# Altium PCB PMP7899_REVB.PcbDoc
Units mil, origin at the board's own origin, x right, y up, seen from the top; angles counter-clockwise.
Board outline 4000 x 1400 mil, 4 copper layers (Component Side, Signal Layer 1, Signal Layer 2, Solder Side), stack 61.2 mil thick; 67 components, 29 nets, 152 pads, 45 vias.
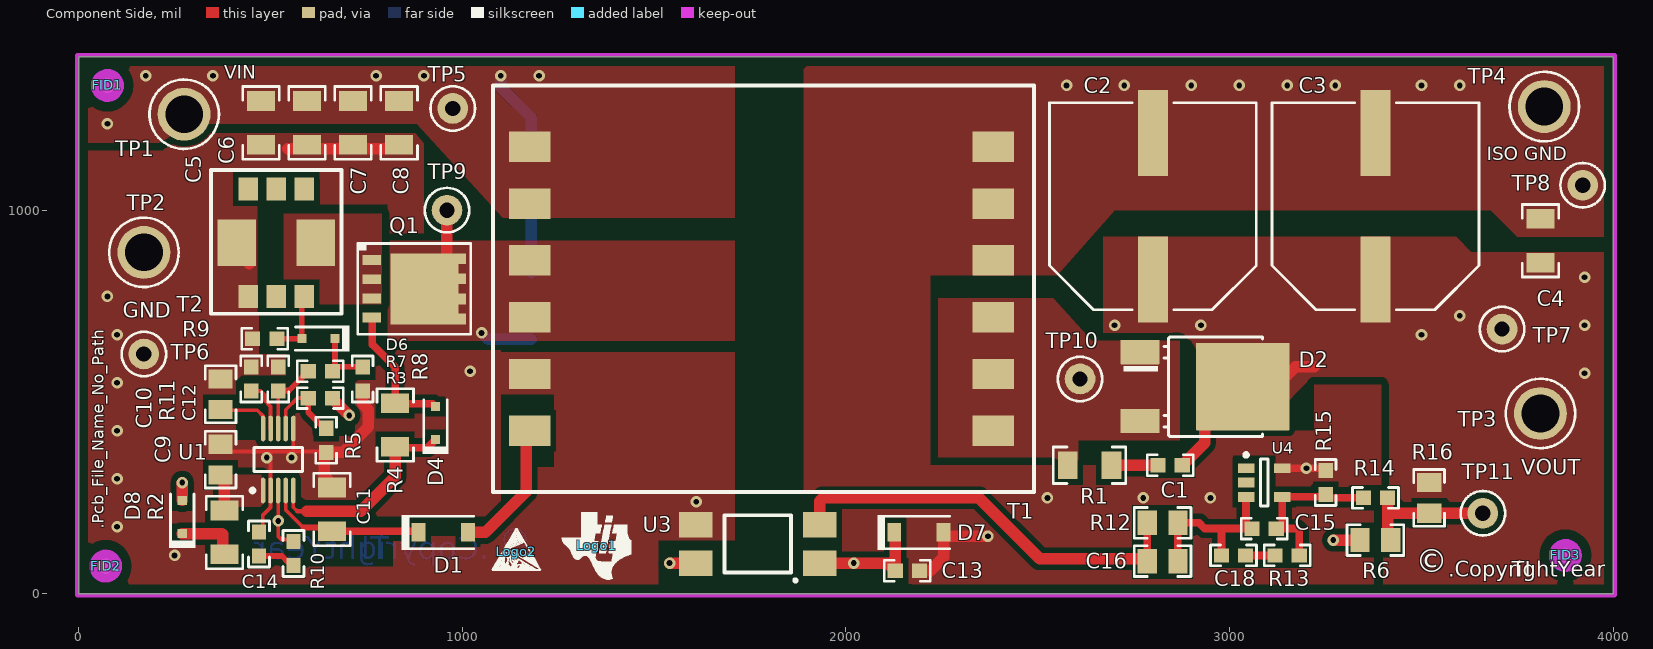
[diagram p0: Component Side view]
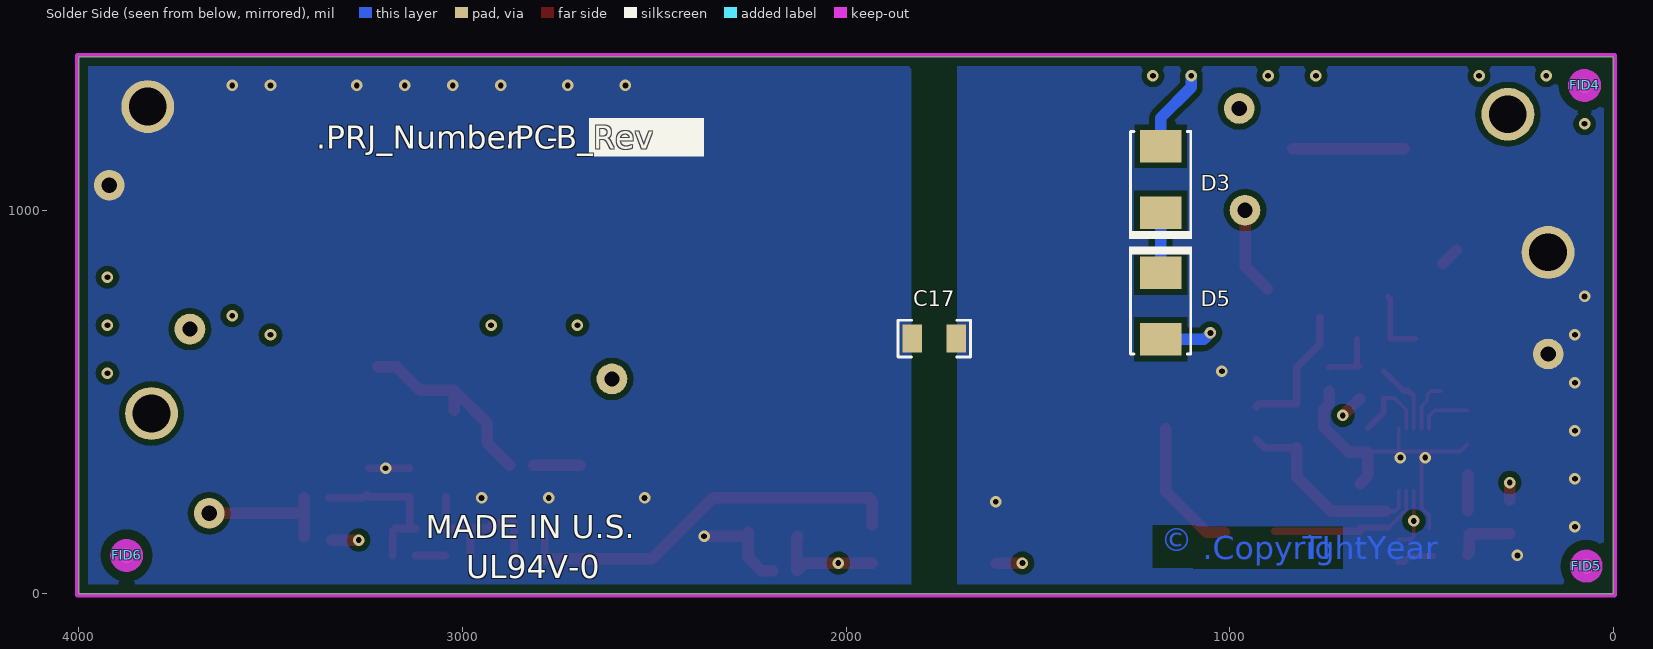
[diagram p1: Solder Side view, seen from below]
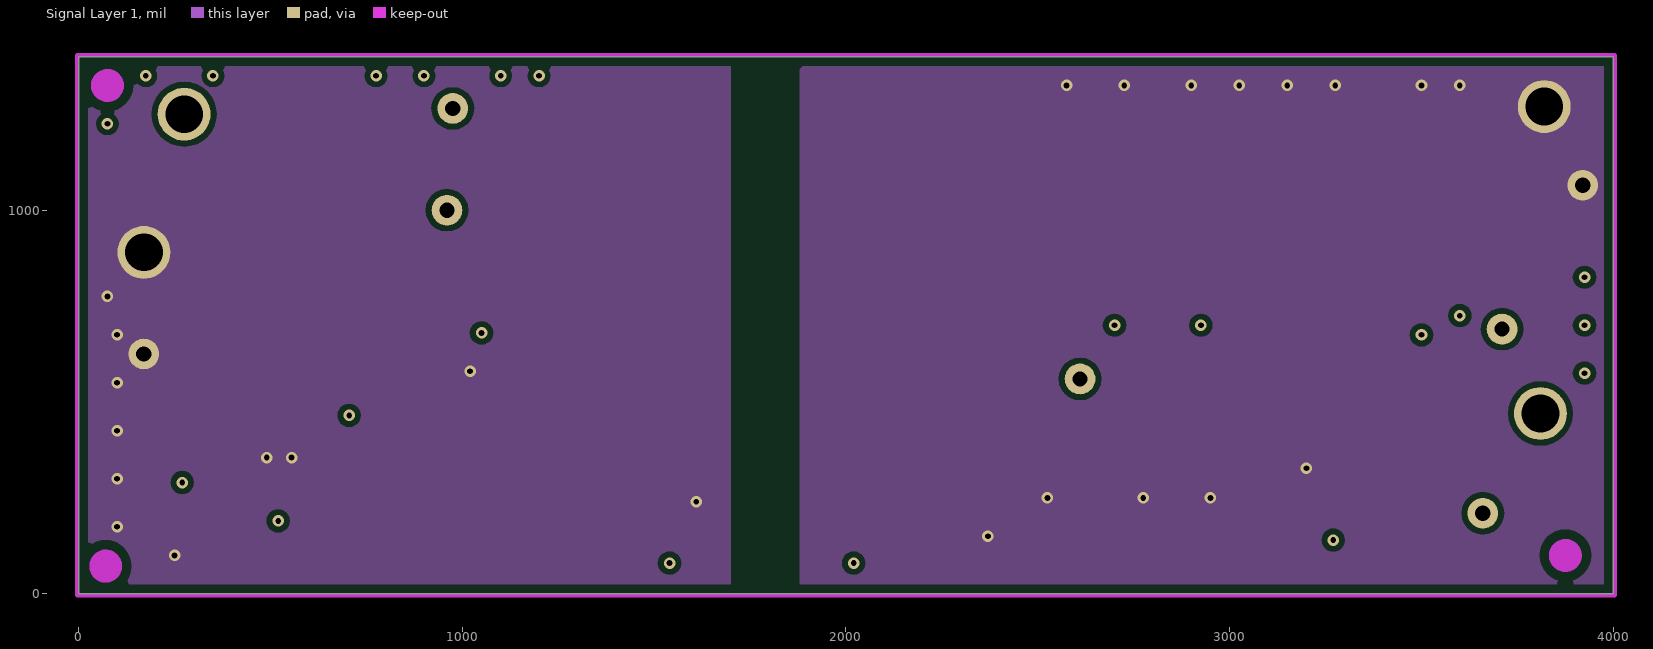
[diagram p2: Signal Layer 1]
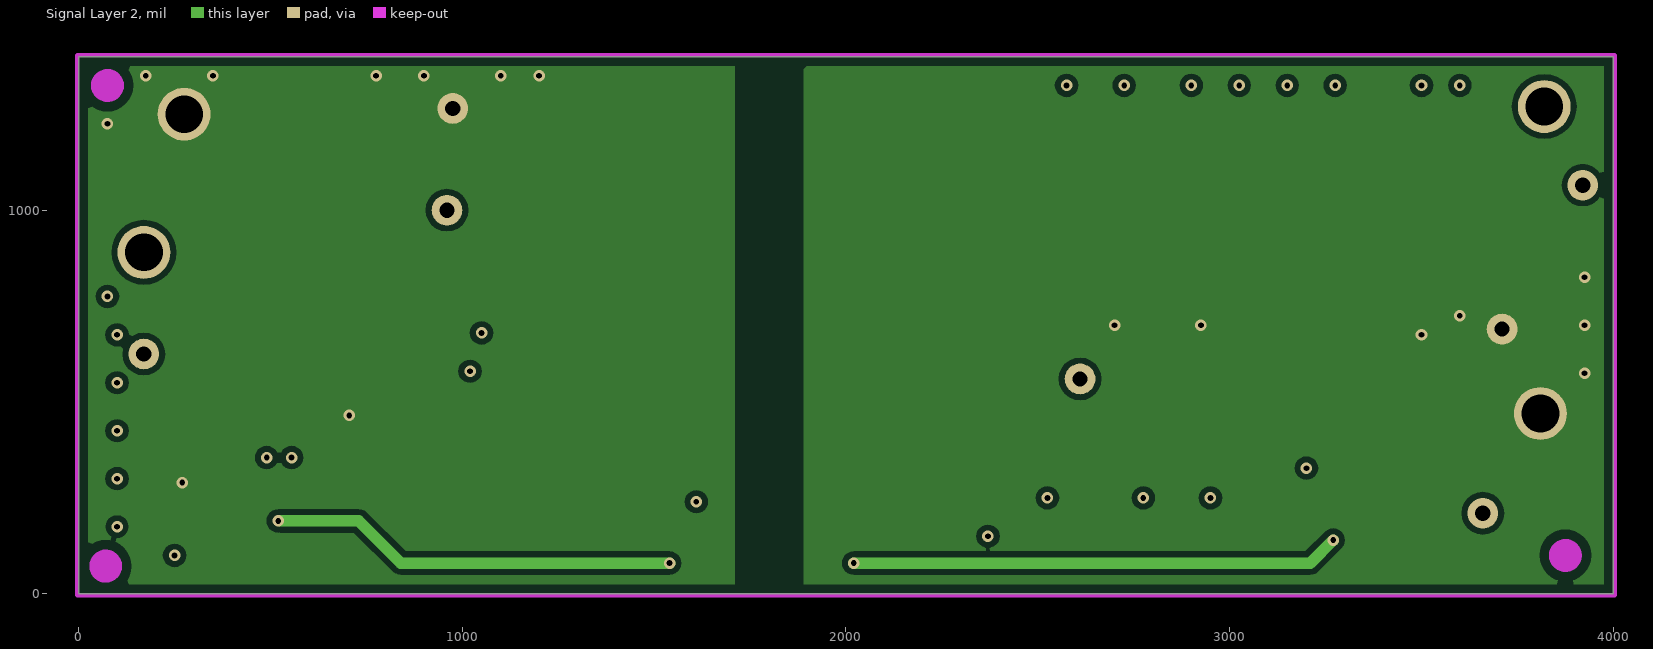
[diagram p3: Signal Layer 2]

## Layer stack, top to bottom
Top Solder: solder mask 0.4, Solder Resist, Dk 3.5
Component Side: signal copper 1.4
Dielectric 1: core 12.5, FR-4, Dk 4.8
Signal Layer 1: signal copper 0.7
Dielectric 2: core 32, FR-4, Dk 4.2
Signal Layer 2: signal copper 0.7
Dielectric 3: core 12.5, FR-4, Dk 4.2
Solder Side: signal copper 1.4
Bottom Solder: solder mask 0.4, Solder Resist, Dk 3.5

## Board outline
0,0 4000,0 4000,1400 0,1400

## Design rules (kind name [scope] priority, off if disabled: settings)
AcuteAngle [All] p1: minimum=4.50000000000000E+0001 checktracksonly=FALSE
AssemblyTestPointUsage [All] p1: valid=2
Clearance Clearance_Poly_to_Poly [IsRegion vs IsRegion] p1: gap=20
Clearance Clearance_Keepouts [((IsTrack Or IsArc) And Not InPoly) And IsFree and IsKeepOut vs ((IsTrack Or IsArc) And Not InPoly) And IsFree and IsKeepOut] p2: gap=0
Clearance Clearance_BoardEdge_MountingHoles [OnCopper and InComponentClass('Mounting Holes') vs IsKeepOut] p3: gap=40
Clearance Clearance_BoardEdge_Poly [OnCopper and InPoly vs IsKeepOut] p4: gap=25
Clearance Clearance_BoardEdge [OnCopper and Not InComponentClass('Logo') and not InComponentClass('FiducialMark') and not InRegion(1000,500,4000,800) and Not IsKeepout vs IsKeepOut] p5: gap=35
Clearance Clearance_Poly [InPolygon] p6: gap=15
Clearance [All] p7: gap=7.87
ComponentClearance ComponentClearance_MountingHoles_FiducialMarks [InComponentClass('Mounting Holes') vs InComponentClass('FiducialMark')] p1: gap=50 collisioncheckmode=3 verticalgap=10 showdistances=FALSE
ComponentClearance ComponentClearance_Shunt [InComponentClass('Header') vs InComponentClass('Shunt')] p2: gap=0 collisioncheckmode=3 verticalgap=0 showdistances=FALSE
ComponentClearance ComponentClearance_Logo [InComponentClass('Logo')] p3: gap=50 collisioncheckmode=3 verticalgap=10 showdistances=FALSE
ComponentClearance ComponentClearance_ScrewToNut [(HasFootprint('NY PMS 440 0025 PH')) vs (HasFootprint('Keystone_1902C'))] p4: gap=5 collisioncheckmode=3 verticalgap=10 showdistances=FALSE
ComponentClearance ComponentClearance_MountingHoles [InComponentClass('Mounting Holes')] p5: gap=250 collisioncheckmode=3 verticalgap=100000 showdistances=FALSE
ComponentClearance ComponentClearance_SmallPassives [HasFootprint('0201*') or HasFootprint('0402*') or HasFootprint('0508') or HasFootprint('0603*') or HasFootprint('0612') or HasFootprint('0805*') or HasFootprint('0815*') or HasFootprint('0830*') or HasFootprint('1206*') or HasFootprint('1210*') or HasFootprint('1808*') or HasFootprint('1812*') or HasFootprint('1825*') or HasFootprint('2010*') or HasFootprint('2220*') or HasFootprint('2225*') or HasFootprint('2512*') or HasFootprint('2728*') or HasFootprint('3518*') vs HasFootprint('0201*') or HasFootprint('0402*') or HasFootprint('0508') or HasFootprint('0603*') or HasFootprint('0612') or HasFootprint('0805*') or HasFootprint('0815*') or HasFootprint('0830*') or HasFootprint('1206*') or HasFootprint('1210*') or HasFootprint('1808*') or HasFootprint('1812*') or HasFootprint('1825*') or HasFootprint('2010*') or HasFootprint('2220*') or HasFootprint('2225*') or HasFootprint('2512*') or HasFootprint('2728*') or HasFootprint('3518*')] p6: gap=20 collisioncheckmode=3 verticalgap=10 showdistances=FALSE
ComponentClearance ComponentClearance_THtoSMT [IsThruComponent vs IsSMTComponent] p7: gap=50 collisioncheckmode=3 verticalgap=30 showdistances=FALSE
ComponentClearance ComponentClearance_THtoTH [IsThruComponent vs IsThruComponent] p8: gap=50 collisioncheckmode=3 verticalgap=30 showdistances=FALSE
ComponentClearance [All] p9: gap=20 collisioncheckmode=3 verticalgap=10 showdistances=FALSE
DiffPairsRouting [All] p1: maxlimit=100 minlimit=10 mostfreqgap=10 toplayer_minwidth=15 toplayer_maxwidth=15 toplayer_prefwidth=15 midlayer1_minwidth=15 midlayer1_maxwidth=15 midlayer1_prefwidth=15 midlayer2_minwidth=15 midlayer2_maxwidth=15 midlayer2_prefwidth=15 bottomlayer_minwidth=15 bottomlayer_maxwidth=15 bottomlayer_prefwidth=15 maxuncoupledlength=1000
FabricationTestPointUsage TestPointUsage [All] p1: valid=2 allowmultiple=FALSE
FabricationTestpoint Testpoint [All] p1: side=3 testpointundercomponent=TRUE minsize=40 maxsize=100 preferedsize=60 minholesize=0 maxholesize=40 preferedholesize=32 testpointgrid=1 allowsidetop=TRUE allowsidebottom=TRUE usegrid=TRUE gridtolerance=0.01
FanoutControl Fanout_LCC [IsLCC] p1: bgadir=Out bgaviamode=Centered fanoutstyle=Auto fanoutdirection=Alternating viagrid=1 // Fanout_LCC (Default Rule)
FanoutControl Fanout_BGA [IsBGA] p2: bgadir=Out bgaviamode=Centered fanoutstyle=Auto fanoutdirection=Alternating viagrid=1 // Fanout_BGA (Default Rule)
FanoutControl Fanout_Default [All] p4: bgadir=Out bgaviamode=Centered fanoutstyle=Auto fanoutdirection=Alternating viagrid=1 // Fanout_Default (Default Rule)
FanoutControl Fanout_Small [(CompPinCount < 5)] p5: bgadir=Out bgaviamode=Centered fanoutstyle=Auto fanoutdirection=OutThenIn viagrid=1 // Fanout_Small (Default Rule)
HoleSize [All] p1: absolutevalues=TRUE maxlimit=251 minlimit=8 maxpercent=80.000 minpercent=20.000
MinimumAnnularRing MinimumAnnularRing_ThermalPadVias [IsVia and InAnyComponent] p1: minimumring=5.91
MinimumAnnularRing [All] p2: minimumring=6
MinimumSolderMaskSliver MinimumSolderMaskSliver_Logo [InComponentClass('Logo') vs InComponentClass('Logo')] p1: minsoldermaskwidth=0.7
MinimumSolderMaskSliver [All] p2: minsoldermaskwidth=3.94
PlaneConnect [All] p1: planeconnectstyle=Relief reliefexpansion=10 reliefentries=4 reliefconductorwidth=10 reliefairgap=10
PolygonConnect [All] p1: connectstyle=Direct reliefconductorwidth=10 reliefentries=4 polygonreliefangle="90 Angle" airgapwidth=10
RoutingVias ThermalPadVias [IsVia and InAnyComponent] p1: holewidth=7.87 width=19.68 viastyle="Through Hole" minholewidth=7.87 minwidth=19.68 maxholewidth=12.99 maxwidth=23.62
RoutingVias [All] p2: holewidth=16 width=34 viastyle="Through Hole" minholewidth=7.87 minwidth=26 maxholewidth=40 maxwidth=65
SilkToBoardRegionClearance [Not ((IsComment or IsDesignator) And (Hide <> 'False')) and not InRegion(1000,500,4000,800)] p1:
SilkToSilkClearance SilkToSilkClearance_Pb-FreeLogo [(HasFootprint('Pb-Free_Overlay_Medium') OR HasFootprint('Pb-Free_Overlay_Small')) vs (HasFootprint('Pb-Free_Overlay_Medium') OR HasFootprint('Pb-Free_Overlay_Small'))] p1: silktosilkclearance=0
SilkToSilkClearance [All] p2: silktosilkclearance=5
SilkToSolderMaskClearance "Silk to Solder Mask Opening" [All] p1: minsilkscreentomaskgap=1 clearancetoexposedcopper=FALSE
SolderMaskExpansion [All] p1: expansion=1.97
UnpouredPolygon [All] p1: allowunpoured=FALSE
Width [All] p1: maxlimit=100 minlimit=6 preferedwidth=10 checkconnectedcopper=TRUE
14 further rules are at their usual default settings.

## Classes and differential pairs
component class FiducialMark: FID1 FID2 FID3 FID4 FID5 FID6
component class Logo: Logo1

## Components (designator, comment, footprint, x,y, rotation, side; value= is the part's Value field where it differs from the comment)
C1 "DNP" 0603 2845,335 r180 top
C2 "EEV-FK1J151Q" SM_RADIAL_H13 2800,1010 r90 top
C3 "EEV-FK1J151Q" SM_RADIAL_H13 3380,1010 r90 top
C4 "C3216X7R2A105M" 1206 3810,920 r90 top
C5 "GRM31CR71E106KA12L" 1206 475,1227.52 r270 top
C6 "GRM31CR71E106KA12L" 1206 595,1227.52 r270 top
C7 "GRM31CR71E106KA12L" 1206 715,1227.52 r270 top
C8 "GRM31CR71E106KA12L" 1206 835.32,1227.52 r270 top
C9 "C2012X5R1E105K" 0805_HV 370,350 r90 top
C10 "C2012C0G1E103J" 0805_HV 370,520 r90 top
C11 "GRM31CR61E106KA12L" 1206 660,220 r90 top
C12 "C1608C0G1H101J" 0603 520,560 r90 top
C13 "GRM188R61C105KA93D" 0603 2160,60 r0 top
C14 "DNP" 0603 470,130 r90 top
C15 "C1608C0G2A101J" 0603 3090,170 r0 top
C16 "DNP" 0805_HV 2825,85 r180 top
C17 "C1206C102KFRACTU" 1206 1770,665 r180 bottom
C18 "C0603C104J3RACTU" 0603 3010,100 r180 top
D1 "1N4148W-7-F" SOD-123 950,160 r0 top
D2 "MURHD560T4G" DPAK 2900,540 r0 top
D3 "1SMB5939BT3G" SMB 1180,1080 r90 bottom
D4 "DNP" sod-323 930,445 r90 top
D5 "MBRS1100T3G" SMB 1180,750 r270 bottom
D6 "BAT54HT1G" sod-323 625,665 r180 top
D7 "MMSZ4699-V" SOD-123 2190,160 r0 top
D8 "BAT54HT1G" sod-323 270,200 r90 top
FID1 "Fiducial" Fiducial10-20 75,1325 r0 top
FID2 "Fiducial" Fiducial10-20 70.46,72.11 r0 top
FID3 "Fiducial" Fiducial10-20 3875,100 r0 top
FID4 "Fiducial" Fiducial10-20 75,1325 r180 bottom
FID5 "Fiducial" Fiducial10-20 70.46,72.11 r180 bottom
FID6 "Fiducial" Fiducial10-20 3875,100 r180 bottom
Logo1 "Texas Instruments" TI_Symbol_Overlay_Small 1350,125 r0 top
Logo2 "ESD Susceptible" ESD_Overlay_Small 1140,110 r0 top
Q1 "BSC067N06LS3 G" PG-TDSON-8 875,795 r0 top
R1 "DNP" 1206 2635,335 r180 top
R2 "CRCW12063R30JNEA" 1206 380,160 r270 top
R3 "CRCW060346K4FKEA" 0603 630,510 r0 top
R4 "CRCW12060000Z0EA" 1206 825,440 r270 top
R5 "CRCW060310K0FKEA" 0603 645,400 r90 top
R6 "CRCW080510K0FKEA" 0805_HV 3380,140 r0 top
R7 "CRCW06031K00FKEA" 0603 630,580 r0 top
R8 "CRCW06032R74FKEA" 0603 740,560 r90 top
R9 "CRCW060310K0FKEA" 0603 485,665 r0 top
R10 "DNP" 0603 560,105 r270 top
R11 "CRCW060349K9FKEA" 0603 450,560 r270 top
R12 "CRCW0805499RFKEA" 0805_HV 2825,185 r0 top
R13 "CRCW06038K25FKEA" 0603 3150,100 r180 top
R14 "CRCW060340K2FKEA" 0603 3380,250 r0 top
R15 "CRCW06031K05FKEA" 0603 3250,290 r90 top
R16 "ERJ-6GEYJ470V" 0805_HV 3520,250 r90 top
T1 "NA6264-AL" NA62XX-AL 1780,795 r0 top
T2 "PA1005.100NLT" PA1005.XXXNL 515,915 r0 top
TP1 "VIN" Keystone1502-2 275,1250 r0 top
TP2 "GND" Keystone1502-2 170,890 r0 top
TP3 "VOUT" Keystone1502-2 3810,470 r0 top
TP4 "ISO GND" Keystone1502-2 3820,1270 r0 top
TP5 "5000" Keystone5000 975,1265 r0 top
TP6 "5001" Keystone5001 170,625 r0 top
TP7 "5000" Keystone5000 3710,690 r0 top
TP8 "5001" Keystone5001 3920,1065 r0 top
TP9 "5002" Keystone5002 960,1000 r0 top
TP10 "5002" Keystone5002 2610,560 r0 top
TP11 "5002" Keystone5002 3660,210 r0 top
U1 "LM5022MME/NOPB" MUB10A_N 520,350 r90 top
U3 "PS2501L-1-L-A" PS2501L 1770,130 r180 top
U4 "LMV431ACM5/NOPB" MF05A_N 3090,290 r0 top

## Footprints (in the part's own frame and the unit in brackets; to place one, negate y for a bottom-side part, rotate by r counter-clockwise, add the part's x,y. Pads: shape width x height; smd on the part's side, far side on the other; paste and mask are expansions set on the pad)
0603 [mm] "0603 from SM-752 data"
  rect 1x0.95 smd: 1(-0.8,0) 2(0.8,0)
  silkscreen extent -1.52,-0.69 1.52,0.69, body extent -0.87,-0.47 0.87,0.47, height 0.85
0805_HV [mil] "0805 with 30mil clearance between pads"
  rect 50x63 smd: 1(-40,0) 2(40,0)
  silkscreen extent -74,-40 74,40, body extent -43,-29 43,29, height 43
1206 [mm] "1206 from SM-752 data"
  rect 1.3x1.85 smd: 1(-1.45,0) 2(1.45,0)
  silkscreen extent -2.4,-1.21 2.4,1.21, body extent -1.7,-0.9 1.7,0.9, height 1.35
DPAK [mm] "D-PAK, 3-Pads, Body 6.22x6.73mm (max), TO-252AA using nominal STEP model"
  rrect6% 2.6x1.6 smd: 1(-3.4,2.28) 3(-3.4,-2.28)
  rrect2% 6.2x5.8 smd paste-2.9: 4(3.4,0)
  silkscreen extent -4.5,-3.3 4.7,3.28, body extent -3.86,-3.29 5.84,3.29, height 2.48
ESD_Overlay_Small [mil]
  silkscreen extent -62,-48 64,61
Fiducial10-20 [mm]
  round 1 smd paste-0.5 mask+0.5: 1(0,0)
  Keep-Out Layer circle w1.178: c0,0 r0.5
Keystone1502-2 [mm] "Double Turret"
  round 3.5 hole 2.5: 1(0,0)
  silkscreen extent -2.3,-2.3 2.3,2.3, body extent -1.61,-1.61 1.61,1.61, height 5.56
Keystone5000 [mil] "For Keystone 500x miniature loop terminals"
  round 80 hole 40: 1(0,0)
  silkscreen extent -58,-58 58,58, body extent -49,-49 49,49, height 182
Keystone5001 [mil] "For Keystone 500x miniature loop terminals"
  round 80 hole 40: 1(0,0)
  silkscreen extent -58,-58 58,58, body extent -49,-49 49,49, height 182
Keystone5002 [mil] "For Keystone 500x miniature loop terminals"
  round 80 hole 40: 1(0,0)
  silkscreen extent -58,-58 58,58, body extent -49,-49 49,49, height 182
MF05A_N [mm] "SOT23, 5-Leads, Body 2.9x1.6mm, Pitch 0.95mm, Lead Span 2.8mm, IPC Medium Density"
  rect 1.1x0.65 smd: 1(-1.2,0.95) 2(-1.2,0) 3(-1.2,-0.95) 4(1.2,-0.95) 5(1.2,0.95)
  silkscreen extent -1.32,-1.55 0.25,1.95, body extent -0.9,-1.55 0.9,1.55, height 1.19
MUB10A_N [mm] "TSSOP, 10-Leads, Body 3x3mm, Pitch 0.5mm, IPC Medium Density"
  oval 1.7x0.3 smd: 1(-2.05,1) 2(-2.05,0.5) 3(-2.05,0) 4(-2.05,-0.5) 5(-2.05,-1) 6(2.05,-1) 7(2.05,-0.5) 8(2.05,0) 9(2.05,0.5) 10(2.05,1)
  silkscreen extent -2.17,-1.6 0.8,1.82, body extent -1.6,-1.6 1.6,1.6, height 1.09
NA62XX-AL [mil] "COILCRAFT TRANFORMER"
  round 60 on Top Overlay: 0(-750,370)
  rect 108x79 smd: 1(-604,370) 2(-604,222) 3(-604,74) 4(-604,-74) 5(-604,-222) 6(-604,-370) 7(604,-370) 8(604,-222) 9(604,-74) 10(604,74) 11(604,222) 12(604,370)
  silkscreen extent -700,-530 710,530, body extent -700,-530 710,530, height 560
PA1005.XXXNL [mil] "PULSE ENGINEERING PA1005.XXXNL SERIES"
  round 30 on Top Overlay: 0(-145,-225)
  rect 50x60 smd: 1(-73,-140) 2(0,-140) 3(73,-140) 4(73,140) 5(0,140) 6(-73,140)
  rect 100x120 smd: 7(103,0) 8(-103,0)
  silkscreen extent -170,-185 170,190, body extent -170,-185 170,190, height 190
PG-TDSON-8 [mm] "Infineon recommended land pattern"
  rect 1.2x0.65 smd: 1(-2.825,1.905) 2(-2.825,0.635) 3(-2.825,-0.635) 4(-2.825,-1.905)
  rect 0.5x0.7 smd: 5(3.175,-2) 6(3.175,-0.675) 7(3.175,0.675) 8(3.175,2)
  rect 4.5x4.7 smd paste-2.25: 9(0.675,0)
  silkscreen extent -3.74,-3 3.74,3, body extent -3.17,-2.89 3.17,2.9, height 1.1
PS2501L [mm] "NEC optocoupler"
  rect 2.2x1.7 smd: 1(-4.1,1.27) 2(-4.1,-1.27) 3(4.1,-1.27) 4(4.1,1.27)
  silkscreen extent -2.57,-1.9 2.2,2.49, body extent -3.5,-2.47 3.5,2.47, height 3.8
SM_RADIAL_H13 [mm] "12.5 x 13.5mm:  Panasonic H13"
  rect 5.7x2 smd: 1(-4.85,0) 2(4.85,0)
  silkscreen extent -6.85,-6.85 6.85,6.85, body extent -6.85,-6.85 6.85,6.85, height 14
SMB [mil] "Molded Diode, 2-Leads, Body 5.4x3.6mm, IPC Medium Density, based on OnSemi component dimensions"
  rect 85x107.99 smd: 1(-87.01,0) 2(87.01,0)
  silkscreen extent -155,-82 125,82, body extent -106,-71 106,71, height 91
SOD-123 [mm] "On Semi recommended land pattern"
  rect 0.915x1.22 smd: 1(-1.637,0) 2(1.637,0)
  silkscreen extent -2.74,-1.17 2.03,1.17, body extent -1.93,-0.9 1.93,0.9, height 1.35
sod-323 [mm] "NXP recommended land pattern"
  rect 0.6x0.6 smd paste-0.05: 1(-1.1,0) 2(1.1,0)
  silkscreen extent -2.06,-0.86 1.53,0.86, body extent -1.3,-0.67 1.3,0.68, height 1.1
TI_Symbol_Overlay_Small [mil]
  silkscreen extent -90,-88 91,88

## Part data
C1: library part C1608C0G2A101J, "CAP, CERM, 100pF, 100V, +/-5%, C0G/NP0, 0603"
C2 C3: "CAP, AL, 150uF, 63V, +/-20%, 0.16 ohm, SMD"
C4: "CAP, CERM, 1uF, 100V, +/-20%, C Series, 1206"
C5 C6 C7 C8: "CAP, CERM, 10uF, 25V, +/-10%, X7R, 1206"
C9: "CAP, CERM, 1uF, 25V, +/-10%, X5R, 0805"
C10: "CAP, CERM, 0.01uF, 25V, +/-5%, C0G/NP0, 0805"
C11: "CAP, CERM, 10uF, 25V, +/-10%, X5R, 1206"
C12: "CAP, CERM, 100pF, 50V, +/-5%, C0G/NP0, 0603"
C13: "CAP, CERM, 1uF, 16V, +/-10%, X5R, 0603"
C14: library part C0603C104K3RACTU, "CAP, CERM, 0.1uF, 25V, +/-10%, X7R, 0603"
C15: "CAP, CERM, 100pF, 100V, +/-5%, C0G/NP0, 0603"
C16: library part C2012X7R1H102K, "CAP, CERM, 1000 pF, 50 V, +/- 10%, X7R, 0805"
C17: "CAP CER 1000PF 1.5KV X7R 1206"
C18: "CAP, CERM, 0.1uF, 25V, +/-5%, X7R, 0603"
D1: "Diode, Ultrafast, 100V, 0.15A, SOD-123"
D2: "Ultra-Fast Diode 600V, 5A, DPAK"
D3: "Diode, Zener, 39 V, 550 mW, SMB"
D4: library part BAT54HT1G, "Diode, Schottky, 30V, 0.2A, SOD-323"
D5: "Diode, Schottky, 100 V, 1 A, SMB"
D6 D8: "Diode, Schottky, 30V, 0.2A, SOD-323"
D7: "Diode, Zener, 12V, 500mW, SOD-123"
FID1 FID2 FID3 FID4 FID5 FID6: "Fiducial mark.  There is nothing to buy or mount."
Logo1: library part TI_Logo, "Texas Instrument Corporate Signature"
Logo2: library part ESD_Susceptible, "ESD Susceptible Symbol"
Q1: "MOSFET, N-CH, 60V, 50A, PG-TDSON-8"
R1: library part CRCW1206100RFKEA, "RES, 100, 1%, 0.25 W, 1206"
R2: "RES, 3.3, 5%, 0.25 W, 1206"
R3: "RES, 46.4k ohm, 1%, 0.1W, 0603"
R4: "RES, 0 ohm, 5%, 0.25W, 1206"
R5 R9: "RES, 10.0k ohm, 1%, 0.1W, 0603"
R6: "RES, 10.0k ohm, 1%, 0.125W, 0805"
R7: "RES, 1.00k ohm, 1%, 0.1W, 0603"
R8: "RES, 2.74, 1%, 0.1 W, 0603"
R10: library part CRCW06031K00FKEA, "RES, 1.00k ohm, 1%, 0.1W, 0603"
R11: "RES, 49.9k ohm, 1%, 0.1W, 0603"
R12: "RES, 499 ohm, 1%, 0.125W, 0805"
R13: "RES, 8.25 k, 1%, 0.1 W, 0603"
R14: "RES, 40.2k ohm, 1%, 0.1W, 0603"
R15: "RES, 1.05 k, 1%, 0.1 W, 0603"
R16: "RES, 47, 5%, 0.125 W, 0805"
T1: "COILCRAFT TRANSFORMER"
T2: "XFRMR CURR SENSE 2.0MH 1:100 SMD"
TP1 TP2 TP3 TP4: library part 1502-2, "Terminal, Turret, TH, Double"
TP5 TP7: "Test Point, TH, Miniature, Red"
TP6 TP8: "Test Point, TH, Miniature, Black"
TP9 TP10 TP11: "Test Point, TH, Miniature, White"
U1: "60V Low Side Controller for Boost and SEPIC, 10-pin MSOP, Pb-Free"
U3: "High Isolation Voltage Single Transistor Type OptoCoupler 200-400% CTR"
U4: "Low-Voltage (1.24V) Adjustable Precision Shunt Regulators, 5-pin SOT-23, Pb-Free"

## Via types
v1: diameter 30, hole 15, Component Side to Solder Side, 45 vias

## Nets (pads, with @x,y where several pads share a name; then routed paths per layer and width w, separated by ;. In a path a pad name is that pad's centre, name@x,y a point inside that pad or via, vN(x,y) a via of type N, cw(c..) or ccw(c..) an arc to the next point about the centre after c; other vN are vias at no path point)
COMP: R10.1 U1.3 U3.4 | length 1292
  Component Side w10: U1.3 v1(520,190) 520,150 528.5,141.5 R10.1@560,141.5
  Component Side w30: v1(1540,80) U3.4
  Signal Layer 2 w30: v1@525,190 730,190 840,80 v1(1540,80)
CS: C12.1 R7.1 U1.8 | length 188.3
  Component Side w10: U1.8 C12.1@520,521.46
  Component Side w15: C12.1@527.05,521.46 535.59,530 547.2,530 547.2,528.7 R7.1
GND: C5.2 C6.2 C7.2 C8.2 C9.2 C10.2 C11.2 C12.2 C14.2 C17.2 R5.1 R8.1 R9.1 R11.1 T1.5 T2.1 T2.8 TP2.1 TP6.1 U1.2 U1.6 U3.3 | length 1208.1
  Component Side w10: C9.2@380,390 399.37,370.63 500,370.63 ; C14.2@480,171.5 480,205 500.31,225.31 U1.2 500.31,370.31 500,370.63 ; U1.6 559.37,370.63 ; R5.1@640,368.5 637.87,370.63 559.37,370.63 ; 500,370.63 559.37,370.63
  Component Side w30: T2.8@410,895 T2.8@445,860 ; 545.32,1160.43 C8.2@835.32,1160.43 ; C11.2@660,287.09 640,307.09 640,368.5 R5.1 688.5,368.5 755,435 755,480 740,495 R8.1
  other v1: 250,100 100,175 1610,240 100,300 490,355 555,355 100,425 100,550 1020,580 100,675 75,775
"ISO GND": C2.2 C3.2 C4.2 C13.2 C17.1 D7.2 R15.2 T1.10 T1.11 T1.12 TP4.1 TP8.1 U4.5 | length 354
  Component Side w20: U4.5 R15.2@3244.09,327.4
  Component Side w30: C13.2 2220,60 2255,95 2254.47,95.53 D7.2 ; D7.2@2266.05,150 2340,150 v1(2370,150)
  other v1: 2525,250 2775,250 2950,250 3200,327.4 2575,1325 2725,1325 2900,1325 3025,1325 3150,1325 3275,1325 3500,1325 3600,1325
NetC1_2: C1.2 R1.1 | length 121.4
  Component Side w30: R1.1 C1.2
NetC13_1: C13.1 D7.1 R6.1 U3.1 | length 1641.5
  Component Side w30: U3.1 v1(2020,80) 2108.5,80 C13.1 2128.5,147.03 D7.1@2125.53,150 ; v1(3270,140) R6.1
  Signal Layer 2 w30: v1(2020,80) 3210,80 v1(3270,140)
NetC14_1: C14.1 R10.2 | length 98.1
  Component Side w15: C14.1 530.04,98.5 546.04,82.5 R10.2@560,82.5 ; C14.1@478.54,98.5 C14.1@480,98.5
NetC15_1: C15.1 C16.1 C18.2 R12.2 U4.3 | length 458.8
  Component Side w20: C16.1 R12.2 2920,185 2935,170 2978.5,170 ; C18.2 2978.5,170 ; U4.3 3042.76,185.75 C15.1 2978.5,170
NetC15_2: C15.2 R13.1 R14.1 R15.1 U4.4 | length 426
  Component Side w20: C15.2 3175,170 3181.5,163.5 R13.1 ; C15.2@3137.24,170 U4.4 3244.09,252.6 R15.1 3258.5,250 R14.1
NetC16_2: C16.2 R12.1 U3.2 | length 1084.8
  Component Side w20: C16.2 R12.1
  Component Side w30: U3.2 1931.42,241.42 1940,250 2346,250 2505,91 2784,91 C16.2@2785,90
NetC18_1: C18.1 R13.2 | length 77
  Component Side w20: C18.1@3044.94,100 R13.2@3121.95,100
NetD1_2: D1.2 T1.6 | length 359.4
  Component Side w30: D1.2 1060,160 1166,266 T1.6@1166,430
NetD2_1: D2.1 D2.3 R1.2 T1.7 T1.8 T1.9 TP10.1
NetD3_1: D3.1 D5.1 | length 156
  Solder Side w30: D5.1 D3.1
NetD4_2: D4.2 Q1.4 R4.1 | length 358.1
  Component Side w20: Q1.4 765,718.78 765,650 825,590 825,495 923.31,495 D4.2
NetD5_2: D5.2 Q1.5 Q1.6 Q1.7 Q1.8 Q1.9 T1.3 T1.4 TP9.1 | length 366.4
  Component Side w30: Q1.9 960,853.43 TP9.1@959.82,1000.12
  Solder Side w30: v1(1050,680) 1067.01,662.99 D5.2
NetD6_1: D6.1 R7.2 R8.2 | length 154.8
  Component Side w15: D6.1 668.31,596.81 662.99,591.5 R8.2 R8.2@741.5,590
NetD6_2: D6.2 R9.2 T2.3 | length 177.8
  Component Side w15: R9.2 D6.2 581.69,768.69 T2.3
NetD8_1: D8.1 R2.2 | length 159.9
  Component Side w30: D8.1 373.31,156.69 375,155 375,107.91 R2.2
NetQ1_1: Q1.1 Q1.2 Q1.3 T2.7
NetR6_2: R6.2 R14.2 R16.1 TP11.1 | length 349.8
  Component Side w30: R6.2@3411.5,148.5 3411.5,210 ; R14.2 3411.5,210 ; TP11.1@3659.82,210.12 3411.5,210
OUT: D4.1 R4.2 U1.5 | length 540.5
  Component Side w10: U1.5 559.37,225.63 570,215
  Component Side w12: 570,215 595,215
  Component Side w20: R4.2@825,380.94 909.25,380.94 D4.1
  Component Side w30: 595,215 735,215 825,305 R4.2@825,380.94
RT: R11.2 U1.9 | length 133.1
  Component Side w10: R11.2 474.76,528.5 485,518.27 485,503.5 500.31,488.19 U1.9
SS: C10.1 U1.10 | length 139.6
  Component Side w10: C10.1@380,478.5 465.51,478.5 480.63,463.39 U1.10
UVLO: R3.1 R5.2 U1.7 | length 216
  Component Side w10: U1.7 539.68,479.68 570,510 R3.1
  Component Side w15: R3.1 598.5,472.99 R5.2@640,431.5
VCC: C11.1 D1.1 U1.4 | length 412.6
  Component Side w10: U1.4 539.68,218.58 585.35,172.91
  Component Side w15: 585.35,172.91 C11.1@660,172.91
  Component Side w20: C11.1 D1.1@882.62,162.91
VIN: C5.1 C6.1 C7.1 C8.1 D3.2 D8.2 R3.2 T1.1 T1.2 TP1.1 TP5.1 | length 317.3
  Component Side w30: D8.2 v1(270,290) ; R3.2@661.5,508.5 v1@700,470
  Solder Side w30: v1(1100,1350) 1100,1320 1180,1240 D3.2
  other v1: 705,465 75,1225 175,1350 350,1350 775,1350 900,1350 1200,1350
"VIN U1": C9.1 R2.1 U1.1 | length 92.9
  Component Side w30: R2.1 C9.1@380,310
VOUT: C1.1 C2.1 C3.1 C4.1 D2.4 R16.2 TP3.1 TP7.1 | length 530.6
  Component Side w30: C1.1 2935,393.5 2935,444.51 D2.4@3020.49,530 ; D2.4@3020.49,479 D2.4@3020.49,530 ; 3220,591.5 3171.5,591.5 3110,530 D2.4@3020.49,530
  other v1: 3925,575 3500,675 2700,700 2925,700 3925,700 3600,725 3925,825
pads on no net: FID1.1 FID2.1 FID3.1 FID4.1 FID5.1 FID6.1 T1.0 T2.0 T2.2 T2.4 T2.5 T2.6 U4.1 U4.2

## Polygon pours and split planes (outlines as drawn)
"ISO GND" on Component Side "Top Layer-ISO GND" (solid, pour order 25): 1890,0 1890,265 3376.32,265 3375,263.68 3375,0
"ISO GND" on Component Side "Top Layer-ISO GND" (solid, remove dead copper, pour order 27): 4000,1400 1890,1400 1890,265 2355,265 2490,125 3010,128.54 3011.26,360.87 3120,360 3120,280 3395,278.54 3395,545 3220,545 3220,425 2955,425 2876.5,335 2220,335 2220,830 2550.65,830 2700,1000 3680,1000 3750,930 4000,930
NetD2_1 on Component Side "Top Layer-D2_1" (solid, remove dead copper, pour order 29): 2240,770 2540,770 2640,660 2849.92,659.92 2850,660 2870,659.92 2870,400.08 2605,399.99 2605,340 2240,340
GND on Component Side "Top Layer-GND" (solid, pour order 28): 390,400 560,400 560,470 604.55,470 610,410 720,410 721.3,550 720,550 720,635 1100,635 1100,202.5 575,202.5 575,320 390,319.41
"VIN U1" on Component Side "Top Layer-VIN U1" (solid, remove dead copper, pour order 20): 370,310 370,226.93 473.07,226.93 485,225.98 485,310
VIN on Component Side "Top Layer-VIN" (solid, pour order 19): 0,1175 210,1175 300,1225 881.57,1225 1105,980 1710,980 1710,1400 0,1400
GND on Component Side "Top Layer-GND" (solid, remove dead copper, pour order 24): 0,705 410,705 410,74.14 820,70 820,150 1050,150 1050,330 1240,330 1240,520 1050,520 1050,630 1710,630 1710,140 1510,140 1510,0 0,0
GND on Component Side "Top Layer-GND" (solid, pour order 23): 290,730 470,730 470,625 540,625 540,570 425,570 410,555 410,535 290,535
NetQ1_1 on Component Side "Top Layer-Q1_1" (solid, remove dead copper, pour order 21): 790,755 790,990 535,990 535,785 615,785 615,755
NetD5_2 on Component Side "Top Layer-D5_2" (solid, remove dead copper, pour order 22): 1710,920 1710,660 805,660 805,920
VOUT on Component Side "Top Layer-VOUT" (solid, remove dead copper, pour order 30): 2670,930 3590,930 3630,890 4000,890 4000,0 3400,0 3400,560 3238.85,560 3238.7,550 3200,550 3130,480 3130,430 2920,430 2920,625.71 2900,660 2850,680 2670,680
GND on Component Side "Top Layer-GND" (solid, remove dead copper, pour order 26): 0,675 465,675 465,1080 630,1080 630,1015 805,1015 805,920 900,920 900,1195 895,1200 220,1200 220,1155 0,1155
VIN on Signal Layer 2 "MidLayer2-VIN" (solid, remove dead copper, pour order 31): 0,0 0,1400 1710,1400 1710,0
VOUT on Signal Layer 2 "MidLayer2-VOUT" (solid, remove dead copper, pour order 32): 4005,1400 1890,1400 1890,-5 4000,-5
"ISO GND" on Solder Side "Bottom Layer-ISO GND" (solid, remove dead copper, pour order 34): 4005,1400 1830,1400 1830,0 4005,0
GND on Solder Side "Bottom Layer-GND" (solid, remove dead copper, pour order 33): 1710,1400 0,1400 0,0 1710,0
GND on Signal Layer 1 "MidLayer1-GND" (solid, remove dead copper, pour order 35): -5,1400 1700,1400 1700,0 0,0
"ISO GND" on Signal Layer 1 "MidLayer1-ISO GND" (solid, remove dead copper, pour order 36): 4000,1400 1880,1400 1880,0 4000,0

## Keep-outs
Keep-Out Layer:
  lines w10: 3999.97,1405 0,1405 ccw(c0,1400) -5,1400 -5,0 ccw(c0,0) 0,-5 4000,-5 ccw(c4000,0) 4005,0 4005,1399.98 ccw(c3999.98,1399.98) 3999.98,1405
  text ".Layer_Name" at 577,-858.49 h60

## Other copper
Component Side:
  text ".Layer_Name" at 577,-858.49 h60
Solder Side:
  text "TI" at 810,90 h60
  text ".CopyrightYear" at 1070,90 h60
  text "©" at 1180,90 h105
  text ".Layer_Name" at 577,-858.49 h60

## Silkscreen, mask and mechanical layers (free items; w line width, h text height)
Top Overlay:
  text ".Pcb_File_Name_No_Path" at 65,170 h30 r90
  text ".CopyrightYear" at 3570,45 h40
  text "TI" at 3735,45 h40
  text "©" at 3485,35 h105
  text ".Layer_Name" at 577,-858.49 h60
Bottom Overlay:
  rectangle: 2370,1140 2670,1240
  text "-" at 2780,1160 h60
  text ".PCB_Rev" at 2890,1160 h60
  text ".PRJ_Number" at 3381,1160.5 h60
  text "MADE IN U.S." at 3095,145 h60
  text "UL94V-0" at 2990,40 h60
  text ".Layer_Name" at 577,-858.49 h60
Top Paste:
  text ".Layer_Name" at 577,-858.49 h60
Bottom Paste:
  text ".Layer_Name" at 577,-858.49 h60
Top Solder:
  text ".Layer_Name" at 577,-858.49 h60
  text ".Layer_Name" at 577,-858.49 h60
Bottom Solder:
  text ".Layer_Name" at 577,-858.49 h60
Drill Guide:
  text ".Layer_Name" at 577,-858.49 h60
Mechanical 1:
  the board outline again, w10
  text ".Layer_Name" at 577,-858.49 h60
Mechanical 2:
  rectangle: 125,-400 500,-275
  rectangle: 0,-275 125,-150
  lines w7: 0,-275 1000,-275 ; 125,-400 125,-150 ; 250,-400 250,-150 ; 500,-400 500,-150 ; 750,-400 750,-150 ; 0,-400 0,-150 1000,-150 1000,-400 0,-400
  text ".Layer_Name" at 577,-858.49 h60
Mechanical 3:
  text ".Layer_Name" at 577,-858.49 h60
Mechanical 4:
  text ".Layer_Name" at 577,-858.49 h60
Mechanical 5:
  lines w10: -292,-930.17 6308,-930.17 ; -292,-726.83 6310,-726.83 ; -292,-523.5 -292,-1133.5 3713,-1133.5 6310,-1133.5 6310,-523.5 -291.5,-523.5 -291.5,-1133.5 1284,-1133.5 ; 2173,-1133.5 2173,-523.5 ; 3440,-726.83 3440,-523.5 ; 4280,-726.83 4280,-523.5 ; 4902,-1140 4902,-937.17
  text "COMPONENTS MARKED 'DNP' SHOULD NOT BE POPULATED." at 1153.5,-318.5 h60
  text "ASSEMBLY VARIANT:" at 1153,-434 h60
  text ".VariantName" at 2189,-434 h60
  text "PCB VIEWED FROM TOP SIDE" at -228.5,-655.67 h60
  text "BOARD #:" at 2248,-655.67 h60
  text ".PRJ_Number" at 2793.5,-655.67 h60
  text "REV:" at 3638,-655.67 h60
  text ".PCB_Rev" at 3929.5,-655.67 h60
  text "SVN REV:" at 4476,-655.67 h60
  text ".VersionControl_RevNumber" at 4982,-655.67 h60
  text "PLOT NAME =" at -228.5,-1064.34 h60
  text ".plot_File_Name" at 577,-1064.34 h60
  text "GENERATED    :" at 2250,-1064.34 h60
  text ".Print_Date" at 3119.5,-1064.34 h60
  text ".Print_Time" at 3848.5,-1064.34 h60
  text "TEXAS INSTRUMENTS" at 5113,-1064.34 h60
Mechanical 6:
  lines w10: -292.5,-727.33 6309.5,-727.33 ; -290.5,-930.67 6309.5,-930.67 ; 1115.5,-1140.5 1115.5,-937.67 ; 1737.5,-727.33 1737.5,-524 ; 2577.5,-727.33 2577.5,-524 ; 3844.5,-1134 3844.5,-524 ; 4733.5,-1134 6309,-1134 6309,-524 -292.5,-524 -292.5,-1134 2304.5,-1134 6309.5,-1134 6309.5,-524
  text "COMPONENTS MARKED 'DNP' SHOULD NOT BE POPULATED." at 6102,-318 h60
  text ".VariantName" at 5058,-434 h60
  text "ASSEMBLY VARIANT:" at 6097,-434 h60
  text ".VersionControl_RevNumber" at 1035.5,-656.17 h60
  text "SVN REV:" at 1541.5,-656.17 h60
  text ".PCB_Rev" at 2088,-656.17 h60
  text "REV:" at 2379.5,-656.17 h60
  text ".PRJ_Number" at 3224,-656.17 h60
  text "BOARD #:" at 3769.5,-656.17 h60
  text "PCB VIEWED FROM BOTTOM SIDE" at 6246,-656.17 h60
  text "TEXAS INSTRUMENTS" at 904.5,-1064.84 h60
  text ".Print_Time" at 2169,-1064.84 h60
  text ".Print_Date" at 2898,-1064.84 h60
  text "GENERATED    :" at 3767.5,-1064.84 h60
  text ".plot_File_Name" at 5440.5,-1064.84 h60
  text "PLOT NAME =" at 6246,-1064.84 h60
Mechanical 9:
  drawing of 57 lines, arcs and shapes, not listed
  text "1" at 739.84,8036.5 h70
  text "2" at 3235.5,8036.5 h70
  text "3" at 5724.84,8036.5 h70
  text "4" at 8231.51,8036.5 h70
  text "5" at 10730.5,8036.5 h70
  text "6" at 13235.5,8036.5 h70
  text "A" at -416.5,6893.5 h70
  text "A" at 14383.5,6893.5 h70
  text "B" at -416.5,4513.5 h70
  text "B" at 14383.5,4513.5 h70
  text "C" at -416.5,2138.5 h70
  text "C" at 14383.5,2138.5 h70
  text "PROJECT TITLE:" at 11343.5,277.5 h45
  text ".PRJ_Title" at 11393.5,144.17 h70
  text "DESIGNED FOR:" at 11343.5,-23.5 h45
  text ".PRJ_Customer" at 11393.5,-163.5 h70
  text "D" at -416.5,-231.5 h70
  text "D" at 14383.5,-231.5 h70
  text "FILE NAME:" at 11343.5,-323.5 h45
  text ".PCB_File_Name_No_Path" at 11393.5,-443.5 h70
  text "Texas Instruments (TI) and/or its licensors do not warrant the accuracy or completeness of this specification" at 6374,-605.34 h45
  text "ENGINEER:" at 11343.5,-613.5 h45
  text "LAYOUT BY:" at 12848.5,-613.5 h45
  text "or any information contained therein. TI and/or its licensors do not warrant that this design will meet" at 6329.01,-718 h45
  text ".PRJ_Engineer" at 11393.5,-768.49 h70
  text ".PCB_Layout" at 12899,-768.49 h70
  text "the specifications, will be suitable for your application or fit for any particular purpose, or will operate in" at 6329.01,-830.67 h45
  text ".Layer_Name" at 577,-858.49 h60
  text "ALTIUM DESIGNER VERSION:" at 12848.5,-923.5 h45
  text "an implementation. TI and/or its licensors do not warrant that the design is production worthy. You should" at 6329.01,-943.33 h45
  text "completely validate and test your design implementation to confirm the system functionality for your application." at 6374,-1056 h45
  text ".print_Scale" at 11393.5,-1056.83 h70
  text ".Application_BuildNumber" at 12899,-1056.83 h70
  text "1" at 739.84,-1263.5 h70
  text "2" at 3235.5,-1263.5 h70
  text "3" at 5724.84,-1263.5 h70
  text "4" at 8231.51,-1263.5 h70
  text "5" at 10730.5,-1263.5 h70
  text "6" at 13235.5,-1263.5 h70
Mechanical 10:
  drawing of 185 lines, arcs and shapes, not listed
  text "DESIGN INFORMATION" at 12381.02,5910 h60
  text "MIN. TRACK WIDTH:" at 11736.46,5730 h60
  text "8" at 12832.7,5730 h60
  text "MIL" at 12987.46,5730 h60
  text "MIN. CLEARANCE:" at 11736.46,5598 h60
  text "0.2" at 12772.7,5598 h60
  text "mm" at 12987.46,5598 h60
  text "MIN. VIA PAD SIZE:" at 11736.46,5466 h60
  text "15" at 12802.71,5466 h60
  text "MIL" at 12987.46,5466 h60
  text "0.05mm (2MIL)" at 12431.46,5324.29 h60
  text "MINIMUM ANNULAR RING" at 11407.23,5320 h60
  text "EXTERNAL" at 13139.46,5320 h60
  text "PER" at 11607.23,5202 h60
  text "IPC-D-275 CLASS 2 LEVEL C" at 11827.23,5202 h60
  text "MIL, HOLES" at 13315.46,5089.71 h60
  text "+/-" at 12923,5089 h60
  text "+/-" at 13777,5089 h60
  text "REGISTRATION TOLERANCES:" at 11407.23,5084 h60
  text "METAL" at 12607,5084 h60
  text "5" at 13183.2,5084 h60
  text "3" at 14016.2,5084 h60
  text "MIL" at 14132.46,5084 h60
  text "MATERIAL:" at 11332.46,4874.54 h60
  text "FR-4 High Tg" at 12318.9,4734.21 h60
  text "FR-408" at 11753.46,4725.64 h60
  text "X" at 12165.46,4725.64 h60
  text "OTHER" at 13241.46,4725.64 h60
  text "62 MIL (1.6mm) +/-10%" at 12073.56,4562.92 h60
  text "THICKNESS:" at 11407.23,4558.64 h60
  text "X" at 11945.4,4558.64 h60
  text "OTHER" at 13358.46,4558.64 h60
  text "TOLERANCE:" at 11407.23,4400.64 h60
  text "X" at 12246.53,4400.64 h60
  text "ANSI IPC-6012 TYPE 3 CLASS 2" at 12433.48,4400.64 h60
  text "OTHER +/-" at 12433.46,4244.64 h60
  text "BOW & TWIST:" at 11407.23,4087.64 h60
  text "X" at 12246.53,4087.64 h60
  text "ANSI IPC-6012 TYPE 3 CLASS 2" at 12433.48,4087.64 h60
  text "OTHER +/-" at 12433.46,3929.13 h60
  text "DRILLING:" at 11332.46,3790.64 h60
  text "REFERENCE:" at 11407.23,3673.64 h60
  text "X" at 12055.46,3673.64 h60
  text "AS SHOWN" at 12242.46,3673.64 h60
  text "X" at 12956.46,3673.64 h60
  text "NC_DRILL FILES" at 13093.46,3673.64 h60
  text "PTH MIN COPPER THICKNESS:" at 11407.23,3515.64 h60
  text "X" at 12757.46,3515.64 h60
  text "1MIL" at 12894.46,3515.64 h60
  text "OTHER" at 13391.46,3515.64 h60
  text "BOARD FINISH:" at 11332.46,3356.64 h60
  text "SILKSCREEN:" at 11487.68,3238.64 h60
  text "X" at 12436.46,3238.64 h60
  text "TOP" at 12562.46,3238.64 h60
  text "X" at 12946.46,3238.64 h60
  text "BOTTOM" at 13073.46,3238.64 h60
  text "SILKSCREEN COLOR:" at 11487.68,3071.64 h60
  text "X" at 12435.42,3071.64 h60
  text "WHITE" at 12562.46,3071.64 h60
  text "OTHER" at 13073.46,3071.64 h60
  text "SOLDER RESIST COLOR:" at 11487.68,2901.64 h60
  text "X" at 12055.42,2742.44 h60
  text "GREEN" at 12182.46,2742.44 h60
  text "BLUE" at 12773.46,2742.44 h60
  text "OTHER" at 13311.46,2742.44 h60
  text "IMMERSION GOLD (ENIG)" at 12393.46,2553.92 h60
  text "ENEPIG" at 13731,2550.64 h60
  text "SURFACE FINISH:" at 11332.46,2549.64 h60
  text "X" at 11500,2395 h60
  text "IMM. TIN/SILVER OR EQUIV" at 11662,2392.64 h60
  text "OTHER" at 13093.46,2392.64 h60
  text "ARRAY/PANEL:" at 11332.46,2213.64 h60
  text "X" at 12210,2210 h60
  text "CUT AND TRIM PER MECH LAYER 1" at 12393.46,2209.35 h60
  text "N.C. ROUTE" at 12393.46,2057.64 h60
  text "V. SCORE" at 13259.46,2057.64 h60
  text "CERTIFICATION:" at 11332.46,1920.64 h60
  text "MATERIALS AND WORKMANSHIP FOR ALL PCBS" at 12057.46,1920.64 h60
  text "TO MEET OR EXCEED THE REQUIREMENTS OF:" at 12057.46,1822.64 h60
  text "X" at 11683.96,1686.13 h60
  text "ANSI IPC-A-600F CLASS ->" at 11822.96,1686.13 h60
  text "X" at 13462.02,1686.13 h60
  text "2" at 13580.96,1686.14 h60
  text "1" at 13265.96,1684.64 h60
  text "3" at 13934.96,1684.64 h60
  text "X" at 11686.02,1526.64 h60
  text "UL 94V-0" at 11822.96,1526.64 h60
  text "X" at 12498.02,1526.64 h60
  text "RoHS" at 12634.96,1526.64 h60
  text "OTHER" at 13279.36,1526.64 h60
  text "PER ORDER" at 13676.42,1526.64 h60
  text "ADDITIONAL REQUIREMENTS:" at 11332.46,1385.64 h60
  text "MICROSECTION:" at 11407.23,1270.64 h60
  text "YES" at 12312.96,1270.64 h60
  text "REQUIRED" at 13174.46,1114.49 h60
  text "BARE BOARD ELEC. TEST:" at 11407.23,1111.64 h60
  text "NONE" at 12712.96,1111.64 h60
  text "PER ORDER" at 13766.46,1111.64 h60
  text "X" at 12590,1110 h60
  text "MANUFACTURER'S UL:" at 11407.23,954.64 h60
  text "RAIL" at 12572.96,950.35 h60
  text "METAL" at 13064.77,950.35 h60
  text "X" at 13440,950 h60
  text "SILK" at 13576.46,950.35 h60
  text ".Layer_Name" at 577,-858.49 h60
Mechanical 11:
  lines w10: -292,-930.17 6308,-930.17 ; -292,-726.83 6310,-726.83 ; -292,-523.5 -292,-1133.5 3713,-1133.5 6310,-1133.5 6310,-523.5 -291.5,-523.5 -291.5,-1133.5 1284,-1133.5 ; 2173,-1133.5 2173,-523.5 ; 3440,-726.83 3440,-523.5 ; 4280,-726.83 4280,-523.5 ; 4902,-1140 4902,-937.17
  text "ALL ARTWORK VIEWED FROM TOP SIDE" at -228.5,-655.67 h60
  text "BOARD #:" at 2248,-655.67 h60
  text ".PRJ_Number" at 2793.5,-655.67 h60
  text "REV:" at 3638,-655.67 h60
  text ".PCB_Rev" at 3929.5,-655.67 h60
  text "SVN REV:" at 4476,-655.67 h60
  text ".VersionControl_RevNumber" at 4982,-655.67 h60
  text "LAYER NAME =" at -228.5,-858.49 h60
  text "PLOT NAME =" at -228.5,-1064.34 h60
  text ".plot_File_Name" at 577,-1064.34 h60
  text "GENERATED    :" at 2250,-1064.34 h60
  text ".Print_Date" at 3119.5,-1064.34 h60
  text ".Print_Time" at 3848.5,-1064.34 h60
  text "TEXAS INSTRUMENTS" at 5113,-1064.34 h60
Mechanical 12:
  drawing of 295 lines, arcs and shapes, not listed
  text "Layer" at 9790.58,7830 h60
  text "Name" at 10200.49,7830 h60
  text "Material" at 11140.23,7830 h60
  text "Thickness" at 12000,7830 h60
  text "Constant" at 12649.83,7830 h60
  text "Board Layer Stack" at 13219.69,7830 h60
  text "1" at 9790.58,7710 h60
  text "Top Overlay" at 10200.49,7710 h60
  text "2" at 9790.58,7590 h60
  text "Top Solder" at 10200.49,7590 h60
  text "Solder Resist" at 11140.23,7590 h60
  text "0.40mil" at 12000,7590 h60
  text "3.5" at 12649.83,7590 h60
  text "3" at 9790.58,7470 h60
  text "Component Side" at 10200.49,7470 h60
  text "Copper" at 11140.23,7470 h60
  text "1.40mil" at 12000,7470 h60
  text "4" at 9790.58,7350 h60
  text "Dielectric 1" at 10200.49,7350 h60
  text "FR-4" at 11140.23,7350 h60
  text "12.50mil" at 12000,7350 h60
  text "4.8" at 12649.83,7350 h60
  text "5" at 9790.58,7230 h60
  text "Signal Layer 1" at 10200.49,7230 h60
  text "Copper" at 11140.23,7230 h60
  text "0.70mil" at 12000,7230 h60
  text "6" at 9790.58,7110 h60
  text "Dielectric 2" at 10200.49,7110 h60
  text "FR-4" at 11140.23,7110 h60
  text "32.00mil" at 12000,7110 h60
  text "4.2" at 12649.83,7110 h60
  text "7" at 9790.58,6990 h60
  text "Signal Layer 2" at 10200.49,6990 h60
  text "Copper" at 11140.23,6990 h60
  text "0.70mil" at 12000,6990 h60
  text "8" at 9790.58,6870 h60
  text "Dielectric 3" at 10200.49,6870 h60
  text "FR-4" at 11140.23,6870 h60
  text "12.50mil" at 12000,6870 h60
  text "4.2" at 12649.83,6870 h60
  text "9" at 9790.58,6750 h60
  text "Solder Side" at 10200.49,6750 h60
  text "Copper" at 11140.23,6750 h60
  text "1.40mil" at 12000,6750 h60
  text "10" at 9790.58,6630 h60
  text "Bottom Solder" at 10200.49,6630 h60
  text "Solder Resist" at 11140.23,6630 h60
  text "0.40mil" at 12000,6630 h60
  text "3.5" at 12649.83,6630 h60
  text "11" at 9790.58,6510 h60
  text "Bottom Overlay" at 10200.49,6510 h60
  text ".Layer_Name" at 577,-858.49 h60
Mechanical 13:
  text ".Layer_Name" at 577,-858.49 h60
Mechanical 14:
  text ".Layer_Name" at 577,-858.49 h60
Mechanical 15:
  text ".Layer_Name" at 577,-858.49 h60
Mechanical 16:
  text ".Layer_Name" at 577,-858.49 h60
Drill Drawing:
  circle w1: c5572.72,3221.04 r24.89
  lines w1: 5547.83,2909.96 5560.27,2909.96 5572.72,2897.52 5585.16,2909.96 5597.6,2909.96 5585.16,2922.4 5597.6,2934.85 5585.16,2934.85 5572.72,2947.29 5560.27,2934.85 5547.83,2934.85 5560.27,2922.4 5547.83,2909.96 ; 5547.83,3096.61 5597.6,3096.61 5572.72,3046.84 5547.83,3096.61
  lines w12: 5480,2852.72 7598.02,2852.72 ; 5480,3300.68 7598.02,3300.68 ; 5850.36,2703.4 5850.36,3450 ; 6207.36,2703.4 6207.36,3450 ; 6868.93,2703.4 6868.93,3450 ; 7153.07,2703.4 7153.07,3450 ; 5480,2703.4 7598.02,2703.4 7598.02,3450 5480,3450 5480,2703.4
  text "Symbol" at 5569.59,3345.48 h72
  text "Quantity" at 5895.16,3345.48 h72
  text "Finished Hole Size" at 6252.16,3345.48 h72
  text "Plated" at 6913.72,3345.48 h72
  text "Hole Type" at 7197.86,3345.48 h72
  text "45" at 5895.16,3196.16 h60
  text "15.00mil (0.381mm)" at 6252.16,3196.16 h60
  text "PTH" at 6913.72,3196.16 h60
  text "Round" at 7197.86,3196.16 h60
  text "7" at 5895.16,3046.84 h60
  text "40.00mil (1.016mm)" at 6252.16,3046.84 h60
  text "PTH" at 6913.72,3046.84 h60
  text "Round" at 7197.86,3046.84 h60
  text "4" at 5895.16,2897.52 h60
  text "98.43mil (2.500mm)" at 6252.16,2897.52 h60
  text "PTH" at 6913.72,2897.52 h60
  text "Round" at 7197.86,2897.52 h60
  text "56 Total" at 5895.16,2748.2 h60
  text ".Layer_Name" at 577,-858.49 h60

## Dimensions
0,0 to 4000,0 on Mechanical 2
0,0 to 0,1400 on Mechanical 2
0,-400 to 1000,-400 on Mechanical 2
